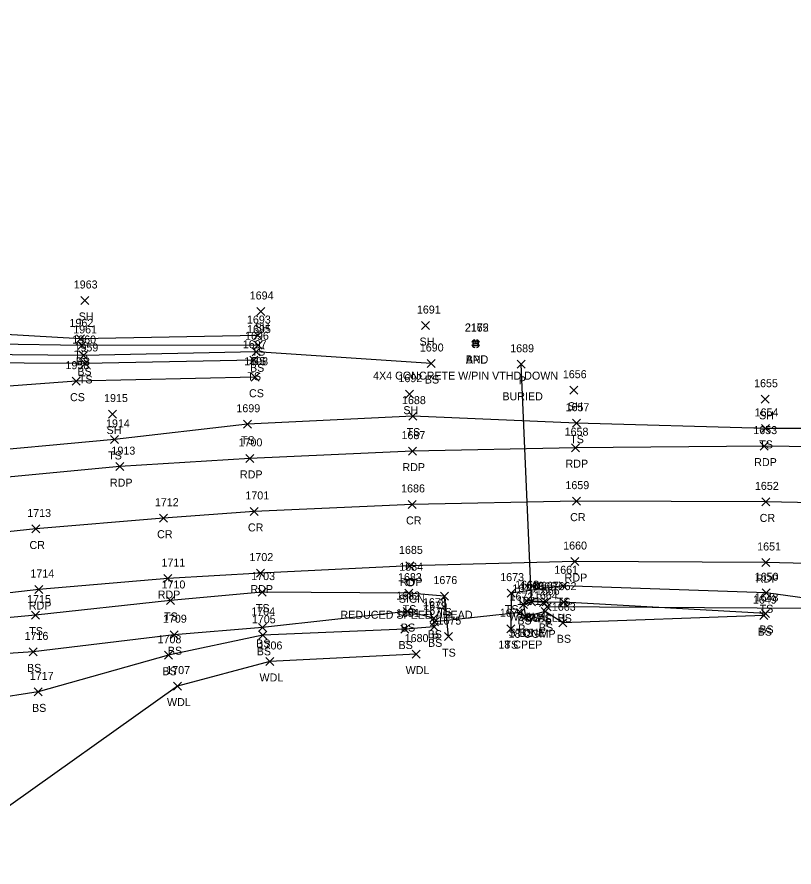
# Model space of a CAD drawing. Extents: x 1600395 to 1603269, y 874955 to 877143.
# Drawn here: x 1602070.6 to 1602264.7, y 875191.6 to 875404 of the extents above; entities that cross this region are included whole.
import ezdxf

# ---------------------------------------------------------------- set-up
doc = ezdxf.new("R2010")
doc.units = 0
for name, color, linetype in [('D_A', 7, 'Continuous'), ('D_C', 7, 'Continuous'), ('D_I', 7, 'Continuous'), ('D_TIC', 7, 'Continuous'), ('DCP', 7, 'Continuous'), ('DHW', 7, 'Continuous'), ('L_A', 7, 'Continuous'), ('L_C', 7, 'Continuous'), ('L_I', 7, 'Continuous'), ('L_TIC', 7, 'Continuous'), ('LAWA', 7, 'Continuous'), ('LELB', 7, 'Continuous'), ('M_A', 7, 'Continuous'), ('M_C', 7, 'Continuous'), ('M_I', 7, 'Continuous'), ('MHBP', 7, 'Continuous'), ('MMP', 7, 'Continuous'), ('P_A', 7, 'Continuous'), ('P_I', 7, 'Continuous'), ('P_TIC', 7, 'Continuous'), ('PET', 7, 'Continuous'), ('PRC', 7, 'Continuous'), ('S_A', 7, 'Continuous'), ('S_C', 7, 'Continuous'), ('S_I', 7, 'Continuous'), ('SSGN', 7, 'Continuous')]:
    doc.layers.add(name, color=color, linetype=linetype)

msp = doc.modelspace()

# ---------------------------------------------------------------- linework, layer by layer
at = {"layer": 'D_TIC'}
for points in [[(1602195.55, 875316.19), (1602197.55, 875318.19)], [(1602197.55, 875316.19), (1602195.55, 875318.19)], [(1602196.83, 875257.13), (1602198.83, 875259.13)], [(1602198.83, 875257.13), (1602196.83, 875259.13)], [(1602198.1, 875256.85), (1602200.1, 875258.85)], [(1602200.1, 875256.85), (1602198.1, 875258.85)], [(1602201.76, 875256.85), (1602203.76, 875258.85)], [(1602203.76, 875256.85), (1602201.76, 875258.85)], [(1602202.04, 875255.61), (1602204.04, 875257.61)], [(1602204.04, 875255.61), (1602202.04, 875257.61)], [(1602195.38, 875254.17), (1602197.38, 875256.17)], [(1602197.38, 875254.17), (1602195.38, 875256.17)], [(1602173.85, 875251.86), (1602175.85, 875253.86)], [(1602175.85, 875251.86), (1602173.85, 875253.86)]]:
    msp.add_lwpolyline(points, dxfattribs=at)
at = {"layer": 'DCP'}
for points in [[(1602199.1, 875257.85), (1602196.55, 875317.19)], [(1602294.81, 875256.02), (1602203.04, 875256.61)], [(1602196.38, 875255.17), (1602174.85, 875252.86)]]:
    msp.add_lwpolyline(points, dxfattribs=at)
at = {"layer": 'DHW'}
msp.add_lwpolyline([(1602202.76, 875257.85), (1602197.83, 875258.13)], dxfattribs=at)
at = {"layer": 'L_TIC'}
for points in [[(1602086.52, 875332.14), (1602088.52, 875334.14)], [(1602088.52, 875332.14), (1602086.52, 875334.14)], [(1602130.47, 875329.39), (1602132.47, 875331.39)], [(1602132.47, 875329.39), (1602130.47, 875331.39)], [(1602171.67, 875325.87), (1602173.67, 875327.87)], [(1602173.67, 875325.87), (1602171.67, 875327.87)], [(1602085.45, 875322.55), (1602087.45, 875324.55)], [(1602087.45, 875322.55), (1602085.45, 875324.55)], [(1602129.78, 875323.37), (1602131.78, 875325.37)], [(1602131.78, 875323.37), (1602129.78, 875325.37)], [(1602085.81, 875320.91), (1602087.81, 875322.91)], [(1602087.81, 875320.91), (1602085.81, 875322.91)], [(1602129.81, 875320.99), (1602131.81, 875322.99)], [(1602131.81, 875320.99), (1602129.81, 875322.99)], [(1602086.23, 875318.39), (1602088.23, 875320.39)], [(1602088.23, 875318.39), (1602086.23, 875320.39)], [(1602129.36, 875319.32), (1602131.36, 875321.32)], [(1602131.36, 875319.32), (1602129.36, 875321.32)], [(1602086.66, 875316.41), (1602088.66, 875318.41)], [(1602088.66, 875316.41), (1602086.66, 875318.41)], [(1602128.74, 875317.21), (1602130.74, 875319.21)], [(1602130.74, 875317.21), (1602128.74, 875319.21)], [(1602173.04, 875316.39), (1602175.04, 875318.39)], [(1602175.04, 875316.39), (1602173.04, 875318.39)], [(1602084.41, 875311.98), (1602086.41, 875313.98)], [(1602086.41, 875311.98), (1602084.41, 875313.98)], [(1602129.11, 875312.96), (1602131.11, 875314.96)], [(1602131.11, 875312.96), (1602129.11, 875314.96)], [(1602208.73, 875309.72), (1602210.73, 875311.72)], [(1602210.73, 875309.72), (1602208.73, 875311.72)], [(1602167.62, 875308.73), (1602169.62, 875310.73)], [(1602169.62, 875308.73), (1602167.62, 875310.73)], [(1602256.46, 875307.46), (1602258.46, 875309.46)], [(1602258.46, 875307.46), (1602256.46, 875309.46)], [(1602093.48, 875303.76), (1602095.48, 875305.76)], [(1602095.48, 875303.76), (1602093.48, 875305.76)], [(1602168.51, 875303.24), (1602170.51, 875305.24)], [(1602170.51, 875303.24), (1602168.51, 875305.24)], [(1602127.15, 875301.21), (1602129.15, 875303.21)], [(1602129.15, 875301.21), (1602127.15, 875303.21)], [(1602209.36, 875301.47), (1602211.36, 875303.47)], [(1602211.36, 875301.47), (1602209.36, 875303.47)], [(1602256.59, 875300.18), (1602258.59, 875302.18)], [(1602258.59, 875300.18), (1602256.59, 875302.18)], [(1602093.95, 875297.42), (1602095.95, 875299.42)], [(1602095.95, 875297.42), (1602093.95, 875299.42)], [(1602206.02, 875260.85), (1602208.02, 875262.85)], [(1602208.02, 875260.85), (1602206.02, 875262.85)], [(1602130.87, 875259.27), (1602132.87, 875261.27)], [(1602132.87, 875259.27), (1602130.87, 875261.27)], [(1602167.51, 875259), (1602169.51, 875261)], [(1602169.51, 875259), (1602167.51, 875261)], [(1602193.04, 875259.01), (1602195.04, 875261.01)], [(1602195.04, 875259.01), (1602193.04, 875261.01)], [(1602256.7, 875259.11), (1602258.7, 875261.11)], [(1602258.7, 875259.11), (1602256.7, 875261.11)], [(1602107.92, 875257.18), (1602109.92, 875259.18)], [(1602109.92, 875257.18), (1602107.92, 875259.18)], [(1602176.41, 875258.28), (1602178.41, 875260.28)], [(1602178.41, 875258.28), (1602176.41, 875260.28)], [(1602198.1, 875256.85), (1602200.1, 875258.85)], [(1602200.1, 875256.85), (1602198.1, 875258.85)], [(1602201.13, 875256.69), (1602203.13, 875258.69)], [(1602203.13, 875256.69), (1602201.13, 875258.69)], [(1602206.18, 875256.76), (1602208.18, 875258.76)], [(1602208.18, 875256.76), (1602206.18, 875258.76)], [(1602167.06, 875254.41), (1602169.06, 875256.41)], [(1602169.06, 875254.41), (1602167.06, 875256.41)], [(1602196.14, 875256.18), (1602198.14, 875258.18)], [(1602198.14, 875256.18), (1602196.14, 875258.18)], [(1602201.51, 875254.43), (1602203.51, 875256.43)], [(1602203.51, 875254.43), (1602201.51, 875256.43)], [(1602074.25, 875253.52), (1602076.25, 875255.52)], [(1602076.25, 875253.52), (1602074.25, 875255.52)], [(1602173.74, 875252.75), (1602175.74, 875254.75)], [(1602175.74, 875252.75), (1602173.74, 875254.75)], [(1602196.64, 875253.08), (1602198.64, 875255.08)], [(1602198.64, 875253.08), (1602196.64, 875255.08)], [(1602196.64, 875253.08), (1602198.64, 875255.08)], [(1602198.64, 875253.08), (1602196.64, 875255.08)], [(1602256.17, 875253.39), (1602258.17, 875255.39)], [(1602258.17, 875253.39), (1602256.17, 875255.39)], [(1602256.58, 875253.94), (1602258.58, 875255.94)], [(1602258.58, 875253.94), (1602256.58, 875255.94)], [(1602256.58, 875253.94), (1602258.58, 875255.94)], [(1602258.58, 875253.94), (1602256.58, 875255.94)], [(1602130.89, 875250.44), (1602132.89, 875252.44)], [(1602132.89, 875250.44), (1602130.89, 875252.44)], [(1602173.83, 875250.59), (1602175.83, 875252.59)], [(1602175.83, 875250.59), (1602173.83, 875252.59)], [(1602173.83, 875250.59), (1602175.83, 875252.59)], [(1602175.83, 875250.59), (1602173.83, 875252.59)], [(1602192.95, 875250.13), (1602194.95, 875252.13)], [(1602194.95, 875250.13), (1602192.95, 875252.13)], [(1602205.98, 875251.61), (1602207.98, 875253.61)], [(1602207.98, 875251.61), (1602205.98, 875253.61)], [(1602108.84, 875248.62), (1602110.84, 875250.62)], [(1602110.84, 875248.62), (1602108.84, 875250.62)], [(1602131.04, 875248.48), (1602133.04, 875250.48)], [(1602133.04, 875248.48), (1602131.04, 875250.48)], [(1602166.46, 875250.04), (1602168.46, 875252.04)], [(1602168.46, 875250.04), (1602166.46, 875252.04)], [(1602177.37, 875248.14), (1602179.37, 875250.14)], [(1602179.37, 875248.14), (1602177.37, 875250.14)], [(1602073.67, 875244.33), (1602075.67, 875246.33)], [(1602075.67, 875244.33), (1602073.67, 875246.33)], [(1602169.27, 875243.78), (1602171.27, 875245.78)], [(1602171.27, 875243.78), (1602169.27, 875245.78)], [(1602107.48, 875243.49), (1602109.48, 875245.49)], [(1602109.48, 875243.49), (1602107.48, 875245.49)], [(1602132.76, 875241.94), (1602134.76, 875243.94)], [(1602134.76, 875241.94), (1602132.76, 875243.94)], [(1602109.66, 875235.79), (1602111.66, 875237.79)], [(1602111.66, 875235.79), (1602109.66, 875237.79)], [(1602074.92, 875234.34), (1602076.92, 875236.34)], [(1602076.92, 875234.34), (1602074.92, 875236.34)]]:
    msp.add_lwpolyline(points, dxfattribs=at)
at = {"layer": 'LAWA'}
msp.add_lwpolyline([(1602170.27, 875244.78), (1602133.76, 875242.94), (1602110.66, 875236.79), (1602064.04, 875203.66), (1602044.2, 875205.89), (1602028.82, 875206.74)], dxfattribs=at)
at = {"layer": 'LELB'}
for points in [[(1602130.78, 875324.37), (1602086.45, 875323.55), (1602047.68, 875325.81), (1602011.49, 875331.95), (1601986.1, 875362.37), (1601981.1, 875381.42), (1601928.66, 875403.97)], [(1602130.81, 875321.99), (1602086.81, 875321.91), (1602044.28, 875322.58), (1602008.89, 875327.29), (1601983.72, 875356.75), (1601975.47, 875363.36), (1601927.66, 875400.9)], [(1602174.04, 875317.39), (1602130.36, 875320.32), (1602087.23, 875319.39), (1602042.6, 875319.82), (1602008.24, 875326.09), (1601982.5, 875352.91), (1601973.75, 875359.58), (1601926.73, 875398.96)], [(1602129.74, 875318.21), (1602087.66, 875317.41), (1602041.95, 875317.61), (1602007.81, 875323.22), (1601980.7, 875349.27), (1601972.05, 875352.54), (1601923.26, 875397.15)], [(1602130.11, 875313.96), (1602085.41, 875312.98), (1602041.79, 875309.76), (1601997.3, 875302.71), (1601977.69, 875304.1), (1601966.14, 875308.98), (1601978.91, 875327.88)], [(1602400.49, 875294.37), (1602361.79, 875296.79), (1602320.07, 875299.51), (1602288.68, 875301.16), (1602257.59, 875301.18), (1602210.36, 875302.47), (1602169.51, 875304.24), (1602128.15, 875302.21), (1602094.95, 875298.42), (1602055.2, 875294.7), (1602015.81, 875291.56), (1601985.08, 875286.24), (1601964.25, 875289.69), (1601956.22, 875288.12), (1601952.74, 875279.27)], [(1602402.24, 875257.27), (1602358.33, 875259.58), (1602318.16, 875261.07), (1602294.09, 875258.79), (1602293.26, 875255.2), (1602257.7, 875260.11), (1602207.02, 875261.85), (1602194.04, 875260.01), (1602193.95, 875251.13)], [(1602178.37, 875249.14), (1602177.41, 875259.28), (1602168.51, 875260), (1602131.87, 875260.27), (1602108.92, 875258.18), (1602075.25, 875254.52), (1602028.81, 875250.19), (1601991.89, 875244.7), (1601984.63, 875238.19), (1601978.7, 875235.57), (1601960.11, 875224.3), (1601939.91, 875209.73), (1601913.86, 875184.56), (1601890.29, 875159.09), (1601878.53, 875149.19), (1601876.37, 875148.08), (1601869.76, 875141.55), (1601836.04, 875101.25), (1601811.3, 875055.59)], [(1602257.58, 875254.94), (1602207.18, 875257.76), (1602202.13, 875257.69), (1602199.1, 875257.85), (1602197.14, 875257.18), (1602197.64, 875254.08)], [(1602174.83, 875251.59), (1602174.74, 875253.75), (1602168.06, 875255.41), (1602131.89, 875251.44), (1602109.84, 875249.62), (1602074.67, 875245.33), (1602029.27, 875242.37), (1601990.91, 875234.92), (1601982.23, 875232.99), (1601966.03, 875218.88), (1601945.4, 875204.55), (1601920.13, 875178.35), (1601896.83, 875152.83)], [(1602257.58, 875254.94), (1602257.17, 875254.39), (1602206.98, 875252.61), (1602202.51, 875255.43), (1602197.64, 875254.08)], [(1602174.83, 875251.59), (1602167.46, 875251.04), (1602132.04, 875249.48), (1602108.48, 875244.49), (1602075.92, 875235.34), (1602028.87, 875228.01), (1601986.72, 875222.76), (1601975.45, 875210.74), (1601952.23, 875195.07)]]:
    msp.add_lwpolyline(points, dxfattribs=at)
at = {"layer": 'MHBP'}
msp.add_lwpolyline([(1602184.58, 875323.05), (1602185.83, 875323.05), (1602185.83, 875321.8), (1602184.58, 875321.8)], close=True, dxfattribs=at)
msp.add_circle((1602185.21, 875322.42), 0.0833, dxfattribs=at)
at = {"layer": 'MMP'}
for p, q in [((1602184.56, 875323), (1602184.91, 875322.65)), ((1602184.59, 875322.36), (1602184.89, 875322.36)), ((1602185.19, 875322.66), (1602185.19, 875322.96)), ((1602185.48, 875322.65), (1602185.83, 875323)), ((1602185.49, 875322.36), (1602185.79, 875322.36)), ((1602184.56, 875321.73), (1602184.91, 875322.08)), ((1602185.19, 875321.76), (1602185.19, 875322.06)), ((1602185.48, 875322.08), (1602185.83, 875321.73))]:
    msp.add_line(p, q, dxfattribs=at)
for start, end in [(105, 165), (15, 75), (195, 255), (285, 345)]:
    msp.add_arc((1602185.19, 875322.36), 1, start, end, dxfattribs=at)
at = {"layer": 'P_TIC'}
for points in [[(1602209.13, 875295.36), (1602211.13, 875297.36)], [(1602211.13, 875295.36), (1602209.13, 875297.36)], [(1602256.26, 875295.75), (1602258.26, 875297.75)], [(1602258.26, 875295.75), (1602256.26, 875297.75)], [(1602127.8, 875292.68), (1602129.8, 875294.68)], [(1602129.8, 875292.68), (1602127.8, 875294.68)], [(1602168.38, 875294.49), (1602170.38, 875296.49)], [(1602170.38, 875294.49), (1602168.38, 875296.49)], [(1602095.32, 875290.62), (1602097.32, 875292.62)], [(1602097.32, 875290.62), (1602095.32, 875292.62)], [(1602209.34, 875282), (1602211.34, 875284)], [(1602211.34, 875282), (1602209.34, 875284)], [(1602168.35, 875281.18), (1602170.35, 875283.18)], [(1602170.35, 875281.18), (1602168.35, 875283.18)], [(1602256.66, 875281.81), (1602258.66, 875283.81)], [(1602258.66, 875281.81), (1602256.66, 875283.81)], [(1602106.17, 875277.74), (1602108.17, 875279.74)], [(1602108.17, 875277.74), (1602106.17, 875279.74)], [(1602128.85, 875279.43), (1602130.85, 875281.43)], [(1602130.85, 875279.43), (1602128.85, 875281.43)], [(1602074.28, 875275.04), (1602076.28, 875277.04)], [(1602076.28, 875275.04), (1602074.28, 875277.04)], [(1602167.76, 875265.82), (1602169.76, 875267.82)], [(1602169.76, 875265.82), (1602167.76, 875267.82)], [(1602208.91, 875266.9), (1602210.91, 875268.9)], [(1602210.91, 875266.9), (1602208.91, 875268.9)], [(1602256.66, 875266.67), (1602258.66, 875268.67)], [(1602258.66, 875266.67), (1602256.66, 875268.67)], [(1602130.43, 875264.02), (1602132.43, 875266.02)], [(1602132.43, 875264.02), (1602130.43, 875266.02)], [(1602107.25, 875262.66), (1602109.25, 875264.66)], [(1602109.25, 875262.66), (1602107.25, 875264.66)], [(1602075.07, 875259.92), (1602077.07, 875261.92)], [(1602077.07, 875259.92), (1602075.07, 875261.92)]]:
    msp.add_lwpolyline(points, dxfattribs=at)
at = {"layer": 'PET'}
for points in [[(1602400.31, 875290.46), (1602361.62, 875292.91), (1602320.01, 875295.06), (1602288.5, 875296.29), (1602257.26, 875296.75), (1602210.13, 875296.36), (1602169.38, 875295.49), (1602128.8, 875293.68), (1602096.32, 875291.62), (1602056.86, 875287.91), (1602018.57, 875283.71), (1601986.25, 875279.93), (1601962.94, 875277.18), (1601953.76, 875275.85), (1601921.23, 875272), (1601886.39, 875267.75)], [(1602402.41, 875260.95), (1602358.59, 875263.43), (1602318.28, 875265.46), (1602288.26, 875266.89), (1602257.66, 875267.67), (1602209.91, 875267.9), (1602168.76, 875266.82), (1602131.43, 875265.02), (1602108.25, 875263.66), (1602076.07, 875260.92), (1602028.17, 875255.41), (1601981.36, 875249.81), (1601955.09, 875246.48), (1601931.43, 875243.62), (1601904.73, 875240.41), (1601882.14, 875236.79), (1601873.56, 875235.88), (1601879.64, 875251.36), (1601886.39, 875267.75)]]:
    msp.add_lwpolyline(points, dxfattribs=at)
at = {"layer": 'PRC'}
msp.add_lwpolyline([(1602402.71, 875276.76), (1602360.41, 875278.94), (1602318.06, 875280.96), (1602289.17, 875282.16), (1602257.66, 875282.81), (1602210.34, 875283), (1602169.35, 875282.18), (1602129.85, 875280.43), (1602107.17, 875278.74), (1602075.28, 875276.04), (1602025.43, 875270.72), (1601983.16, 875265.3), (1601954.29, 875261.32), (1601930.37, 875258.06), (1601901.66, 875254.25), (1601879.64, 875251.36)], dxfattribs=at)
at = {"layer": 'SSGN'}
for p, q in [((1602167.2, 875263.46), (1602170.53, 875263.46)), ((1602168.85, 875262.63), (1602168.85, 875262.63))]:
    msp.add_line(p, q, dxfattribs=at)
msp.add_circle((1602168.85, 875262.63), 0.833, dxfattribs=at)

# ---------------------------------------------------------------- texts
at = {"layer": 'D_A'}
for s, p in [('P', (1602195.93, 875312.19)), ('WALLH', (1602193.42, 875253.13)), ('WALLH', (1602198.35, 875252.85)), ('P', (1602198.48, 875252.85)), ('P', (1602195.76, 875250.17)), ('P', (1602202.42, 875251.61)), ('P', (1602174.23, 875247.86))]:
    msp.add_text(s, height=2, dxfattribs=at).set_placement(p)
at = {"layer": 'D_C'}
for s, p in [('BURIED', (1602191.85, 875308.19)), ('STONE', (1602193.37, 875249.13)), ('18 CPEP', (1602190.84, 875246.17))]:
    msp.add_text(s, height=2, dxfattribs=at).set_placement(p)
at = {"layer": 'D_I'}
for s, p in [('1689', (1602193.8, 875320.19)), ('1668', (1602195.04, 875261.13)), ('1669', (1602196.31, 875260.85)), ('1667', (1602199.97, 875260.85)), ('1666', (1602200.2, 875259.61)), ('1672', (1602193.64, 875258.17)), ('1679', (1602172.1, 875255.86))]:
    msp.add_text(s, height=2, dxfattribs=at).set_placement(p)
at = {"layer": 'L_A'}
for s, p in [('SH', (1602086.01, 875328.14)), ('SH', (1602129.96, 875325.39)), ('SH', (1602171.15, 875321.87)), ('TS', (1602084.86, 875318.55)), ('TS', (1602129.19, 875319.37)), ('BS', (1602085.25, 875316.91)), ('BS', (1602129.25, 875316.99)), ('BS', (1602085.67, 875314.39)), ('BS', (1602128.8, 875315.32)), ('TS', (1602086.07, 875312.41)), ('TS', (1602128.15, 875313.21)), ('BS', (1602172.48, 875312.39)), ('CS', (1602083.85, 875307.98)), ('CS', (1602128.56, 875308.96)), ('SH', (1602208.22, 875305.72)), ('SH', (1602167.11, 875304.73)), ('SH', (1602255.95, 875303.46)), ('SH', (1602092.97, 875299.76)), ('TS', (1602167.92, 875299.24)), ('TS', (1602126.56, 875297.21)), ('TS', (1602208.77, 875297.47)), ('TS', (1602256, 875296.18)), ('TS', (1602093.36, 875293.42)), ('TS', (1602205.43, 875256.85)), ('TS', (1602130.28, 875255.27)), ('TS', (1602166.92, 875255)), ('TS', (1602192.45, 875255.01)), ('TS', (1602256.11, 875255.11)), ('TS', (1602107.33, 875253.18)), ('TS', (1602175.82, 875254.28)), ('BS', (1602197.55, 875252.85)), ('BS', (1602200.57, 875252.69)), ('BS', (1602205.62, 875252.76)), ('BS', (1602166.5, 875250.41)), ('BS', (1602195.58, 875252.18)), ('BS', (1602200.95, 875250.43)), ('TS', (1602073.66, 875249.52)), ('BS', (1602173.18, 875248.75)), ('BS', (1602196.08, 875249.08)), ('BS', (1602196.08, 875249.08)), ('BS', (1602255.61, 875249.39)), ('BS', (1602256.02, 875249.94)), ('BS', (1602256.02, 875249.94)), ('BS', (1602130.33, 875246.44)), ('BS', (1602165.9, 875246.04)), ('BS', (1602173.27, 875246.59)), ('BS', (1602173.27, 875246.59)), ('TS', (1602192.36, 875246.13)), ('BS', (1602205.43, 875247.61)), ('BS', (1602108.28, 875244.62)), ('BS', (1602130.48, 875244.48)), ('TS', (1602176.78, 875244.14)), ('BS', (1602073.11, 875240.33)), ('BS', (1602106.92, 875239.49)), ('WDL', (1602167.68, 875239.78)), ('WDL', (1602131.18, 875237.94)), ('WDL', (1602108.07, 875231.79)), ('BS', (1602074.36, 875230.34))]:
    msp.add_text(s, height=2, dxfattribs=at).set_placement(p)
at = {"layer": 'L_C'}
msp.add_text('18 CGMP', height=2, dxfattribs=at).set_placement((1602193.4, 875248.85))
at = {"layer": 'L_I'}
for s, p in [('1963', (1602084.78, 875336.14)), ('1694', (1602128.73, 875333.39)), ('1691', (1602170.49, 875329.87)), ('1962', (1602083.71, 875326.55)), ('1693', (1602128.04, 875327.37)), ('1961', (1602084.64, 875324.91)), ('1695', (1602128.07, 875324.99)), ('1960', (1602084.4, 875322.39)), ('1696', (1602127.56, 875323.32)), ('1959', (1602084.96, 875320.41)), ('1697', (1602127, 875321.21)), ('1690', (1602171.22, 875320.39)), ('1958', (1602082.71, 875315.98)), ('1698', (1602127.37, 875316.96)), ('1692', (1602165.88, 875312.73)), ('1656', (1602206.94, 875313.72)), ('1655', (1602254.72, 875311.46)), ('1915', (1602092.35, 875307.76)), ('1688', (1602166.77, 875307.24)), ('1657', (1602207.62, 875305.47)), ('1699', (1602125.4, 875305.21)), ('1654', (1602254.85, 875304.18)), ('1914', (1602092.83, 875301.42)), ('1703', (1602129.1, 875263.27)), ('1683', (1602165.77, 875263)), ('1673', (1602191.3, 875263.01)), ('1661', (1602204.8, 875264.85)), ('1650', (1602254.87, 875263.11)), ('1710', (1602106.71, 875261.18)), ('1676', (1602174.62, 875262.28)), ('1669', (1602196.31, 875260.85)), ('1665', (1602199.34, 875260.69)), ('1662', (1602204.39, 875260.76)), ('1670', (1602194.31, 875260.18)), ('1715', (1602073.13, 875257.52)), ('1682', (1602165.32, 875258.41)), ('1678', (1602172, 875256.75)), ('1671', (1602195.47, 875257.08)), ('1671', (1602195.47, 875257.08)), ('1664', (1602199.72, 875258.43)), ('1649', (1602254.42, 875257.39)), ('1648', (1602254.84, 875257.94)), ('1648', (1602254.84, 875257.94)), ('1704', (1602129.12, 875254.44)), ('1677', (1602172.09, 875254.59)), ('1677', (1602172.09, 875254.59)), ('1663', (1602204.2, 875255.61)), ('1709', (1602107.06, 875252.62)), ('1705', (1602129.27, 875252.48)), ('1681', (1602165.28, 875254.04)), ('1674', (1602191.21, 875254.13)), ('1675', (1602175.63, 875252.14)), ('1716', (1602072.49, 875248.33)), ('1708', (1602105.71, 875247.49)), ('1706', (1602130.94, 875245.94)), ('1680', (1602167.44, 875247.78)), ('1707', (1602107.88, 875239.79)), ('1717', (1602073.8, 875238.34))]:
    msp.add_text(s, height=2, dxfattribs=at).set_placement(p)
at = {"layer": 'M_A'}
for s, p in [('APL', (1602182.7, 875317.36)), ('BND', (1602182.69, 875317.42))]:
    msp.add_text(s, height=2, dxfattribs=at).set_placement(p)
at = {"layer": 'M_C'}
msp.add_text('4X4 CONCRETE W/PIN VTHD DOWN', height=2, dxfattribs=at).set_placement((1602159.55, 875313.36))
at = {"layer": 'M_I'}
for s, p in [('2165', (1602182.45, 875325.36)), ('2172', (1602182.51, 875325.42))]:
    msp.add_text(s, height=2, dxfattribs=at).set_placement(p)
at = {"layer": 'P_A'}
for s, p in [('RDP', (1602166.87, 875290.49)), ('RDP', (1602207.62, 875291.36)), ('RDP', (1602254.75, 875291.75)), ('RDP', (1602126.29, 875288.68)), ('RDP', (1602093.81, 875286.62)), ('CR', (1602208.77, 875278)), ('CR', (1602256.1, 875277.81)), ('CR', (1602167.78, 875277.18)), ('CR', (1602105.6, 875273.74)), ('CR', (1602128.28, 875275.43)), ('CR', (1602073.72, 875271.04)), ('RDP', (1602207.39, 875262.9)), ('RDP', (1602166.25, 875261.82)), ('RDP', (1602255.15, 875262.67)), ('RDP', (1602105.74, 875258.66)), ('RDP', (1602128.92, 875260.02)), ('RDP', (1602073.56, 875255.92))]:
    msp.add_text(s, height=2, dxfattribs=at).set_placement(p)
at = {"layer": 'P_I'}
for s, p in [('1658', (1602207.39, 875299.36)), ('1653', (1602254.52, 875299.75)), ('1687', (1602166.64, 875298.49)), ('1700', (1602125.94, 875296.68)), ('1913', (1602094.2, 875294.62)), ('1686', (1602166.55, 875285.18)), ('1659', (1602207.59, 875286)), ('1652', (1602254.92, 875285.81)), ('1701', (1602127.65, 875283.43)), ('1712', (1602105.04, 875281.74)), ('1713', (1602073.16, 875279.04)), ('1685', (1602166.02, 875269.82)), ('1660', (1602207.03, 875270.9)), ('1651', (1602255.49, 875270.67)), ('1702', (1602128.66, 875268.02)), ('1711', (1602106.69, 875266.66)), ('1714', (1602073.94, 875263.92))]:
    msp.add_text(s, height=2, dxfattribs=at).set_placement(p)
at = {"layer": 'S_A'}
msp.add_text('SIGN', height=2, dxfattribs=at).set_placement((1602165.98, 875257.61))
at = {"layer": 'S_C'}
msp.add_text('REDUCED SPEED AHEAD', height=2, dxfattribs=at).set_placement((1602151.4, 875253.61))
at = {"layer": 'S_I'}
msp.add_text('1684', height=2, dxfattribs=at).set_placement((1602166.09, 875265.61))

doc.saveas('drawing.dxf')
